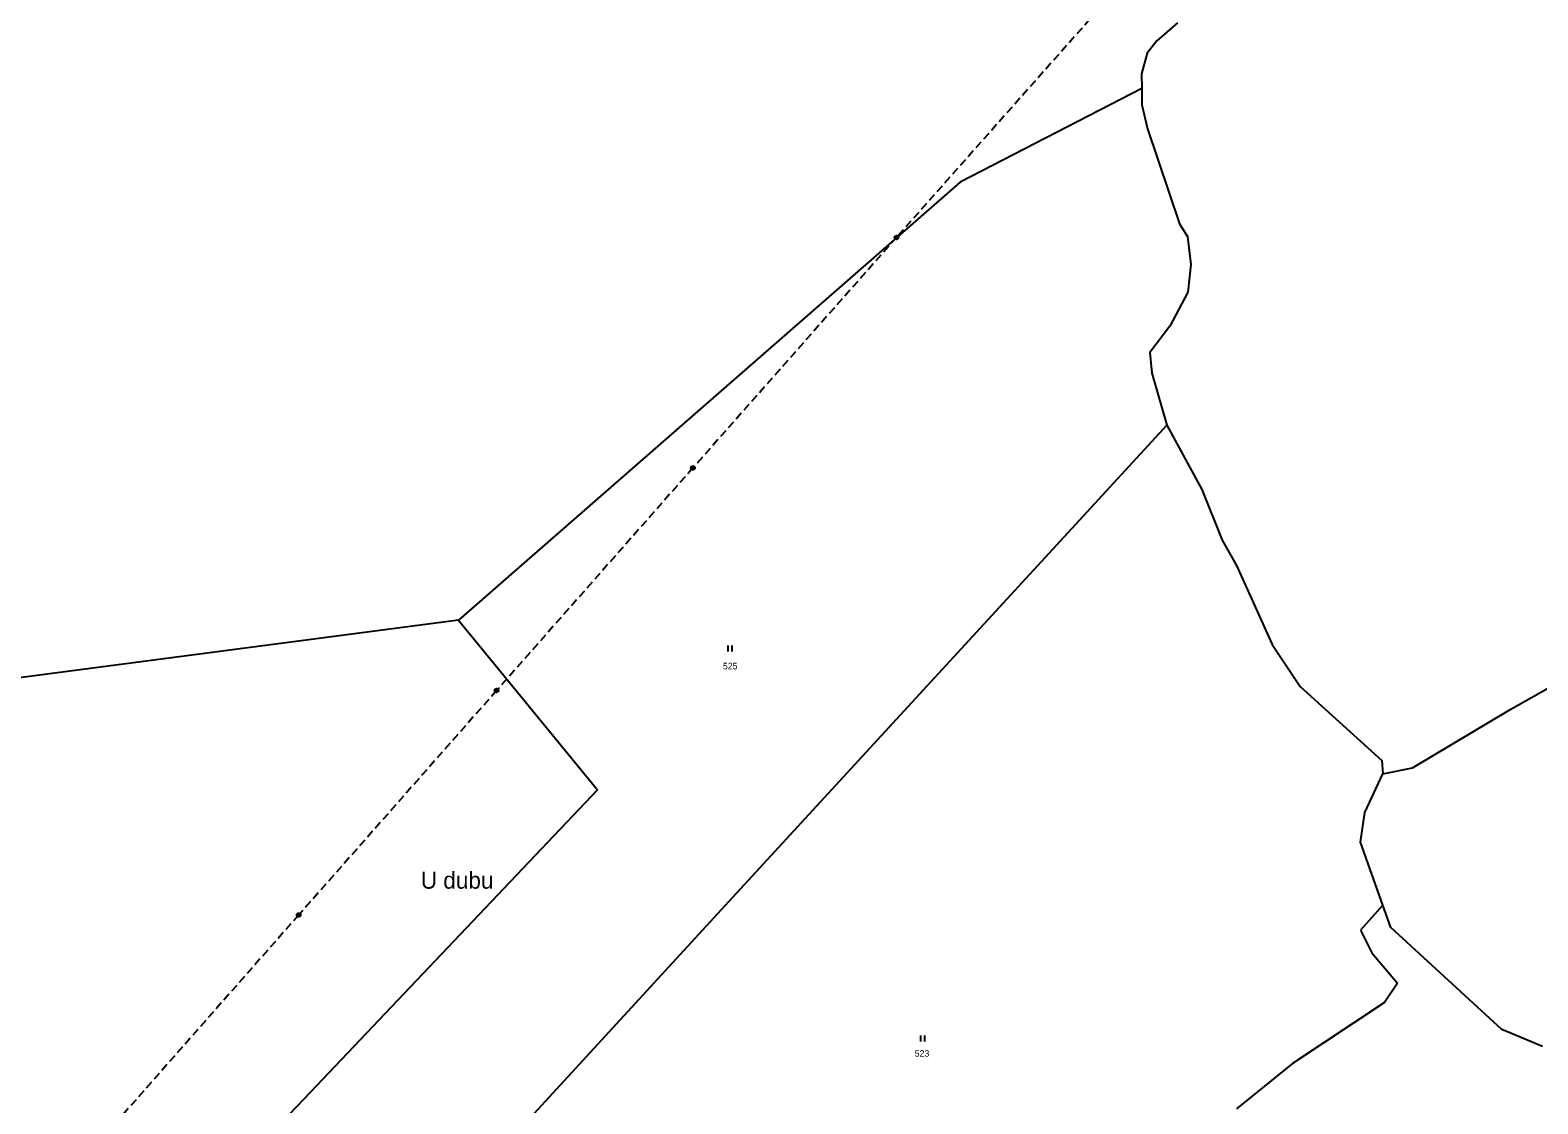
# Model space of a CAD drawing. Extents: x -653193 to -651624, y -1092017 to -1090260.
# Drawn here: x -652409.3 to -652015.8, y -1091141.6 to -1090861.4 of the extents above; entities that cross this region are included whole.
import ezdxf
from ezdxf.enums import TextEntityAlignment as Align

# ---------------------------------------------------------------- set-up
doc = ezdxf.new("R2010")
doc.units = 0
doc.header["$LTSCALE"] = 0.68
doc.linetypes.add('MEDIUM_DASHED', pattern=[4.5, 3, -1.5])
for name, color, linetype, lineweight in [('1', 7, 'Continuous', 25), ('3', 7, 'Continuous', 25), ('6', 7, 'Continuous', 25), ('7', 7, 'Continuous', 13)]:
    doc.layers.add(name, color=color, linetype=linetype, lineweight=lineweight)
doc.layers.add('2', color=7, linetype='Continuous')

msp = doc.modelspace()

# ---------------------------------------------------------------- linework, layer by layer
at = {"layer": '1'}
for p, q in [((-652109.84, -1090859.51), (-652115.21, -1090864.22)), ((-652115.21, -1090864.22), (-652117.79, -1090867.43)), ((-652117.79, -1090867.43), (-652119.24, -1090872.78)), ((-652119.24, -1090872.78), (-652119.2, -1090876.67)), ((-652119.2, -1090876.67), (-652166.57, -1090901.08)), ((-652119.2, -1090876.67), (-652119.16, -1090880.9)), ((-652119.16, -1090880.9), (-652117.68, -1090887.19)), ((-652117.68, -1090887.19), (-652109.37, -1090911.95)), ((-652166.57, -1090901.08), (-652297.45, -1091015.37)), ((-652109.37, -1090911.95), (-652107.21, -1090915.24)), ((-652107.21, -1090915.24), (-652106.38, -1090922.58)), ((-652106.38, -1090922.58), (-652107.2, -1090929.78)), ((-652107.2, -1090929.78), (-652111.83, -1090938.62)), ((-652111.83, -1090938.62), (-652117.12, -1090945.55)), ((-652117.12, -1090945.55), (-652116.54, -1090950.95)), ((-652116.54, -1090950.95), (-652112.61, -1090964.45)), ((-652112.61, -1090964.45), (-652228.92, -1091090.97)), ((-652112.61, -1090964.45), (-652103.53, -1090981.24)), ((-652103.53, -1090981.24), (-652098.19, -1090994.52)), ((-652098.19, -1090994.52), (-652094.46, -1091001.11)), ((-652094.46, -1091001.11), (-652085.13, -1091021.7)), ((-652297.45, -1091015.37), (-652406.81, -1091029.7)), ((-652297.45, -1091015.37), (-652261.23, -1091059.62)), ((-652085.13, -1091021.7), (-652077.86, -1091032.73)), ((-652022.86, -1091038.65), (-651996.02, -1091023.32)), ((-652406.81, -1091029.7), (-652513.84, -1091043.71)), ((-652077.86, -1091032.73), (-652056.52, -1091051.99)), ((-652048.57, -1091053.92), (-652022.86, -1091038.65)), ((-652056.52, -1091051.99), (-652056.26, -1091055.5)), ((-652056.26, -1091055.5), (-652048.57, -1091053.92)), ((-652061.02, -1091065.6), (-652056.26, -1091055.5)), ((-652261.23, -1091059.62), (-652337.88, -1091140.35)), ((-652062.14, -1091073.36), (-652061.02, -1091065.6)), ((-652056.29, -1091089.8), (-652062.14, -1091073.36)), ((-652228.92, -1091090.97), (-652333.63, -1091204.87)), ((-652056.29, -1091089.8), (-652062.14, -1091096.3)), ((-652054.22, -1091095.62), (-652056.29, -1091089.8)), ((-652062.14, -1091096.3), (-652059.17, -1091102.17)), ((-652025.24, -1091122.2), (-652054.22, -1091095.62)), ((-652059.17, -1091102.17), (-652052.45, -1091110.16)), ((-652052.45, -1091110.16), (-652055.85, -1091115.17)), ((-652055.85, -1091115.17), (-652079.85, -1091131.06)), ((-652014.63, -1091126.63), (-652025.24, -1091122.2)), ((-652079.85, -1091131.06), (-652094.43, -1091142.88)), ((-652337.88, -1091140.35), (-652401.48, -1091207.32))]:
    msp.add_line(p, q, dxfattribs=at)
at = {"layer": '3'}
for p, q in [((-652227.091, -1091023.52), (-652227.091, -1091022.02)), ((-652226.09, -1091023.52), (-652226.09, -1091022.02)), ((-652176.811, -1091125.32), (-652176.811, -1091123.82)), ((-652175.81, -1091125.32), (-652175.81, -1091123.82))]:
    msp.add_line(p, q, dxfattribs=at)
at = {"layer": '6', "linetype": 'MEDIUM_DASHED'}
for p, q in [((-652130.7, -1090856.28), (-652183.19, -1090915.5)), ((-652183.19, -1090915.5), (-652236.31, -1090975.65)), ((-652236.31, -1090975.65), (-652287.54, -1091033.75)), ((-652287.54, -1091033.75), (-652339.17, -1091092.32)), ((-652339.17, -1091092.32), (-652387.86, -1091147.62))]:
    msp.add_line(p, q, dxfattribs=at)
at = {"layer": '6'}
for centre, radius in [((-652183.1934, -1090915.4999), 0.5), ((-652183.1934, -1090915.4999), 0.4), ((-652183.1934, -1090915.4999), 0.3), ((-652183.1934, -1090915.4999), 0.2), ((-652183.1934, -1090915.4999), 0.1), ((-652236.3134, -1090975.6499), 0.5), ((-652236.3134, -1090975.6499), 0.4), ((-652236.3134, -1090975.6499), 0.3), ((-652236.3134, -1090975.6499), 0.2), ((-652236.3134, -1090975.6499), 0.1), ((-652287.5434, -1091033.7499), 0.5), ((-652287.5434, -1091033.7499), 0.4), ((-652287.5434, -1091033.7499), 0.3), ((-652287.5434, -1091033.7499), 0.2), ((-652287.5434, -1091033.7499), 0.1), ((-652339.1734, -1091092.3199), 0.5), ((-652339.1734, -1091092.3199), 0.4), ((-652339.1734, -1091092.3199), 0.3), ((-652339.1734, -1091092.3199), 0.2), ((-652339.1734, -1091092.3199), 0.1)]:
    msp.add_circle(centre, radius, dxfattribs=at)

# ---------------------------------------------------------------- texts
at = {"layer": '2'}
for s, p in [('525', (-652226.579, -1091028.215)), ('523', (-652176.529, -1091129.305))]:
    msp.add_text(s, height=1.7, dxfattribs=at).set_placement(p, align=Align.CENTER)
at = {"layer": '7'}
msp.add_text('U dubu', height=4.4, dxfattribs=at).set_placement((-652297.84, -1091085.46), align=Align.CENTER)

doc.saveas('drawing.dxf')
